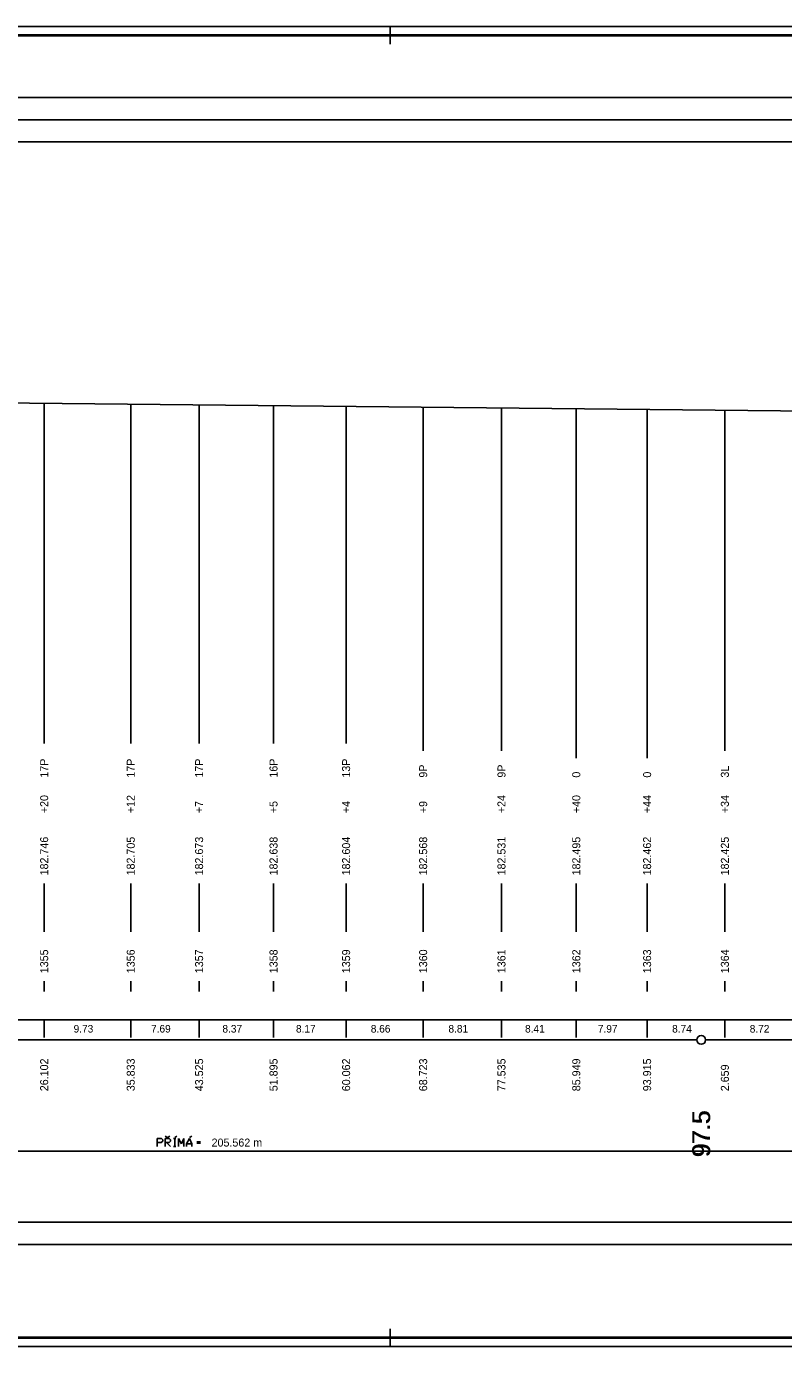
# Model space of a CAD drawing. Extents: x 0 to 10087, y -805 to 297.
# Drawn here: x 2228.2 to 2398.5, y 0 to 297 of the extents above; entities that cross this region are included whole.
import ezdxf

# ---------------------------------------------------------------- set-up
doc = ezdxf.new("R2010")
doc.units = 0
for name, color, linetype in [('CARKY_HODNOT', 7, 'Continuous'), ('KRIV1_CARA', 7, 'Continuous'), ('KRIV1_TEXT', 7, 'Continuous'), ('NIVELETA_CARA', 7, 'Continuous'), ('RAM', 7, 'Continuous'), ('REZERVA', 7, 'Continuous'), ('STAN_CARA', 7, 'Continuous'), ('STAN_PAS', 7, 'Continuous'), ('STAN_TEXT', 7, 'Continuous'), ('TEXT', 7, 'Continuous'), ('TXT_C_BODU', 7, 'Continuous')]:
    doc.layers.add(name, color=color, linetype=linetype)

msp = doc.modelspace()

# ---------------------------------------------------------------- linework, layer by layer
at = {"layer": 'CARKY_HODNOT'}
for p, q in [((2232.2, 138.35), (2232.2, 212.23)), ((2251.67, 138.35), (2251.67, 212.03)), ((2267.05, 138.35), (2267.05, 211.87)), ((2283.79, 138.35), (2283.79, 211.69)), ((2300.12, 138.35), (2300.12, 211.52)), ((2317.45, 138.35), (2317.45, 211.34)), ((2335.07, 138.35), (2335.07, 211.15)), ((2351.9, 138.35), (2351.9, 210.98)), ((2367.83, 138.35), (2367.83, 210.81)), ((2385.32, 138.35), (2385.32, 210.63)), ((2232.2, 135.65), (2232.2, 138.35)), ((2251.67, 135.65), (2251.67, 138.35)), ((2267.05, 135.65), (2267.05, 138.35)), ((2283.79, 135.65), (2283.79, 138.35)), ((2300.12, 135.65), (2300.12, 138.35)), ((2317.45, 134), (2317.45, 138.35)), ((2335.07, 134), (2335.07, 138.35)), ((2351.9, 132.35), (2351.9, 138.35)), ((2367.83, 132.35), (2367.83, 138.35)), ((2385.32, 134), (2385.32, 138.35)), ((2232.2, 93.3), (2232.2, 104.2)), ((2251.67, 93.3), (2251.67, 104.2)), ((2267.05, 93.3), (2267.05, 104.2)), ((2283.79, 93.3), (2283.79, 104.2)), ((2300.12, 93.3), (2300.12, 104.2)), ((2317.45, 93.3), (2317.45, 104.2)), ((2335.07, 93.3), (2335.07, 104.2)), ((2351.9, 93.3), (2351.9, 104.2)), ((2367.83, 93.3), (2367.83, 104.2)), ((2385.32, 93.3), (2385.32, 104.2)), ((2232.2, 79.9), (2232.2, 82.2)), ((2251.67, 79.9), (2251.67, 82.2)), ((2267.05, 79.9), (2267.05, 82.2)), ((2283.79, 79.9), (2283.79, 82.2)), ((2300.12, 79.9), (2300.12, 82.2)), ((2317.45, 79.9), (2317.45, 82.2)), ((2335.07, 79.9), (2335.07, 82.2)), ((2351.9, 79.9), (2351.9, 82.2)), ((2367.83, 79.9), (2367.83, 82.2)), ((2385.32, 79.9), (2385.32, 82.2))]:
    msp.add_line(p, q, dxfattribs=at)
at = {"layer": 'KRIV1_CARA'}
msp.add_line((2066.11, 44), (2477.23, 44), dxfattribs=at)
at = {"layer": 'KRIV1_TEXT'}
for p, q in [((2257.64, 45), (2257.64, 46.8)), ((2257.64, 46.8), (2258.56, 46.8)), ((2258.54, 45.9), (2257.64, 45.9)), ((2258.86, 46.2), (2258.54, 45.9)), ((2258.56, 46.8), (2258.86, 46.49)), ((2258.86, 46.49), (2258.86, 46.2)), ((2259.93, 47.03), (2259.42, 47.37)), ((2259.44, 45), (2259.44, 46.8)), ((2259.44, 46.8), (2260.34, 46.8)), ((2260.34, 45.9), (2259.44, 45.9)), ((2259.74, 45.9), (2260.65, 45)), ((2259.93, 47.03), (2260.44, 47.37)), ((2260.34, 46.8), (2260.65, 46.51)), ((2260.65, 46.2), (2260.34, 45.9)), ((2260.65, 46.51), (2260.65, 46.2)), ((2261.28, 46.79), (2261.85, 46.79)), ((2261.28, 45), (2261.85, 45)), ((2261.56, 47.03), (2262.07, 47.37)), ((2261.56, 45), (2261.56, 46.79)), ((2262.45, 45), (2262.45, 46.79)), ((2262.45, 46.79), (2263.07, 45.6)), ((2263.07, 45.6), (2263.65, 46.79)), ((2263.65, 46.79), (2263.65, 45)), ((2264.86, 46.81), (2264.25, 45.6)), ((2264.25, 45), (2264.25, 45.6)), ((2264.25, 45.6), (2265.45, 45.6)), ((2265.45, 45.6), (2264.86, 46.81)), ((2264.88, 47.03), (2265.39, 47.37)), ((2265.45, 45.6), (2265.45, 45)), ((2266.57, 46.07), (2267.38, 46.07)), ((2266.57, 45.75), (2267.38, 45.75))]:
    msp.add_line(p, q, dxfattribs=at)
at = {"layer": 'NIVELETA_CARA'}
for p, q in [((300, 281), (8321.33, 281)), ((300, 276), (8321.33, 276)), ((300, 271), (8321.33, 271)), ((2122.3, 213.38), (2531.93, 209.09)), ((500, 28), (8321.33, 28)), ((500, 23), (8321.33, 23))]:
    msp.add_line(p, q, dxfattribs=at)
at = {"layer": 'RAM'}
for p, q in [((8636.33, 297), (0, 297)), ((2310, 293), (2310, 297)), ((8634.33, 295.1), (2, 295.1)), ((8634.33, 295), (2, 295)), ((8634.33, 294.9), (2, 294.9)), ((2310, 0), (2310, 4)), ((0, 0), (8636.33, 0)), ((2, 2.1), (8634.33, 2.1)), ((2, 2), (8634.33, 2)), ((2, 1.9), (8634.33, 1.9))]:
    msp.add_line(p, q, dxfattribs=at)
at = {"layer": 'REZERVA'}
msp.add_circle((2380, 69), 1, dxfattribs=at)
at = {"layer": 'STAN_CARA'}
for p, q in [((2181, 69), (2379, 69)), ((2381, 69), (2579, 69))]:
    msp.add_line(p, q, dxfattribs=at)
at = {"layer": 'STAN_PAS'}
for p, q in [((300, 73.5), (8321.33, 73.5)), ((2232.2, 69.5), (2232.2, 73.5)), ((2251.67, 69.5), (2251.67, 73.5)), ((2267.05, 69.5), (2267.05, 73.5)), ((2283.79, 69.5), (2283.79, 73.5)), ((2300.12, 69.5), (2300.12, 73.5)), ((2317.45, 69.5), (2317.45, 73.5)), ((2335.07, 69.5), (2335.07, 73.5)), ((2351.9, 69.5), (2351.9, 73.5)), ((2367.83, 69.5), (2367.83, 73.5)), ((2385.32, 69.5), (2385.32, 73.5))]:
    msp.add_line(p, q, dxfattribs=at)

# ---------------------------------------------------------------- texts
at = {"layer": 'KRIV1_TEXT'}
msp.add_text(' 205.562 m', height=1.8, dxfattribs=at).set_placement((2269.19, 45))
at = {"layer": 'STAN_TEXT'}
for s, p in [('9.73', (2238.82, 70.65)), ('7.69', (2256.24, 70.65)), ('8.37', (2272.3, 70.65)), ('8.17', (2288.84, 70.65)), ('8.66', (2305.67, 70.65)), ('8.81', (2323.14, 70.65)), ('8.41', (2340.37, 70.65)), ('7.97', (2356.75, 70.65)), ('8.74', (2373.46, 70.65)), ('8.72', (2390.92, 70.65))]:
    msp.add_text(s, height=1.7, dxfattribs=at).set_placement(p)
for s, height, p in [('26.102', 1.8, (2233.1, 57.45)), ('35.833', 1.8, (2252.57, 57.45)), ('43.525', 1.8, (2267.95, 57.45)), ('51.895', 1.8, (2284.69, 57.45)), ('60.062', 1.8, (2301.02, 57.45)), ('68.723', 1.8, (2318.35, 57.45)), ('77.535', 1.8, (2335.97, 57.45)), ('85.949', 1.8, (2352.8, 57.45)), ('93.915', 1.8, (2368.73, 57.45)), ('2.659', 1.8, (2386.22, 57.45)), ('    97.5', 4, (2382, 36.84)), ('    97.5', 4, (2382, 36.74)), ('    97.5', 4, (2382, 36.64))]:
    msp.add_text(s, height=height, rotation=90, dxfattribs=at).set_placement(p)
at = {"layer": 'TEXT'}
for s, p in [('17P', (2233.1, 128)), ('17P', (2252.57, 128)), ('17P', (2267.95, 128)), ('16P', (2284.69, 128)), ('13P', (2301.02, 128)), ('9P', (2318.35, 128)), ('9P', (2335.97, 128)), ('0', (2352.8, 128)), ('0', (2368.73, 128)), ('3L', (2386.22, 128)), ('+20', (2233.1, 120)), ('+12', (2252.57, 120)), ('+7', (2267.95, 120)), ('+5', (2284.69, 120)), ('+4', (2301.02, 120)), ('+9', (2318.35, 120)), ('+24', (2335.97, 120)), ('+40', (2352.8, 120)), ('+44', (2368.73, 120)), ('+34', (2386.22, 120)), ('182.746', (2233.1, 106)), ('182.705', (2252.57, 106)), ('182.673', (2267.95, 106)), ('182.638', (2284.69, 106)), ('182.604', (2301.02, 106)), ('182.568', (2318.35, 106)), ('182.531', (2335.97, 106)), ('182.495', (2352.8, 106)), ('182.462', (2368.73, 106)), ('182.425', (2386.22, 106))]:
    msp.add_text(s, height=1.8, rotation=90, dxfattribs=at).set_placement(p)
at = {"layer": 'TXT_C_BODU'}
for s, p in [('1355', (2233.1, 84)), ('1356', (2252.57, 84)), ('1357', (2267.95, 84)), ('1358', (2284.69, 84)), ('1359', (2301.02, 84)), ('1360', (2318.35, 84)), ('1361', (2335.97, 84)), ('1362', (2352.8, 84)), ('1363', (2368.73, 84)), ('1364', (2386.22, 84))]:
    msp.add_text(s, height=1.8, rotation=90, dxfattribs=at).set_placement(p)

doc.saveas('drawing.dxf')
